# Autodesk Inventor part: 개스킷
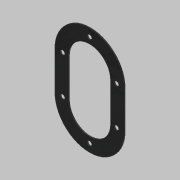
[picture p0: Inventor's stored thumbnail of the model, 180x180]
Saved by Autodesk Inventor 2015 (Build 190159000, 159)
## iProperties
Created: 2019-03
Part Number: 개스킷
Material: 고무
Document SubType Name: Modeling
Designer: mduedu
Density: 1 g/cm^3
Appearance: 고무 - 검은색 - 버전 1.1
Author: mduedu
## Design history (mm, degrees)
sketch "스케치1"
  geometry: L1 (-62, 40)-(62, 40); L2 (62, 40)-(62, -40); L3 (62, -40)-(-62, -40); L4 (-62, -40)-(-62, 40); L5 (-62, 40)-(62, -40); L6 (62, 40)-(-62, -40); 1 further point
  constraints: 12 end point, 2 midpoint, 2 parallel, 1 horizontal, 1 perpendicular
  dimensions: "d21" = 124 distance of L2.end L3.end; "d22" = 80 distance of L1.end L2.end
extrude "돌출1" new body sketch "스케치1" distance "d3" = 1; taper "d4" = 0 deg
fillet "모깎기2"
fillet "모깎기3"
sketch "스케치2" dims "d6" = 48
  geometry: L1 (-24, -22)-(24, -22); L2 (24, -22)-(24, 22); L3 (24, 22)-(-24, 22); L4 (-24, 22)-(-24, -22); L5 (-24, -22)-(24, 22); L6 (24, -22)-(-24, 22); 3 further points
  constraints: 12 end point, 4 midpoint, 2 horizontal alignment, 2 parallel, 1 horizontal, 1 perpendicular, 4 other
  dimensions: "d8" = 22 distance from line of L3 point (0, 0)
extrude "돌출2" cut sketch "스케치2" stored distance "d9" = 1; taper "d10" = 0 deg
sketch "스케치3"
  geometry: L1 (24, -22)-(24, 22) reference; L2 (-24, 22)-(-24, -22) reference; L3 (31, 22)-(31, -22); L4 (-31, -22)-(-31, 22); A1 r 24 centre (0, 22) between (24, 22) and (-24, 22) reference; A2 r 24 centre (0, -22) between (-24, -22) and (24, -22) reference; A3 r 31 centre (0, 22) between (31, 22) and (-31, 22); A4 r 31 centre (0, -22) between (-31, -22) and (31, -22); 7 further points
  constraints: 6 point on circle, 4 coincident, 4 end point, 2 centre point, 3 other
  dimensions: "d26" = 62 distance between parallel lines of L3 L4; "d28" = 7 distance between parallel lines of L4 L2 (derived); "d29" = 48 distance between parallel lines of L1 L2 (derived); "d30" = 31 radius of A3 (derived)
hole "구멍1" sketch "스케치3" at (0, 53), (31, 22), (31, -22), (0, -53), (-31, -22), (-31, 22) diameter "d14" = 5; stored, may be unused: countersink angle "d18" = 90 deg, drill point angle "d20" = 118 deg; dims "d15" = 6, "d16" = 4, "d17" = 2, "d19" = 8
node "솔리드1"
